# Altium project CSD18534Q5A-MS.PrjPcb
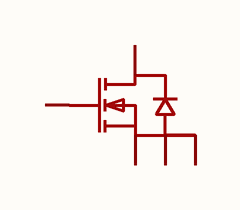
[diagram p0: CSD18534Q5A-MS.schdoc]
1 sheet, 1 parts. Net scope: global (net labels, ports and power ports of the same name join across sheets).

## Sheet CSD18534Q5A-MS.schdoc
size 127 x 101 mm

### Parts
Q?  csd18534q5a-ms  [TDSON-8_L5.9-W5.2-P1.27-BL-1]  (value not drawn)

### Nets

Not connected (* = marked no-connect by the designer): Q? 1(S) 2(S) 3(S) 4(G) 5(D)

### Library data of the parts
Q? = csd18534q5a-ms: 数量:1个N沟道;漏源电压(Vdss):60V;连续漏极电流(Id):65A;导通电阻(RDS(on)):8mΩ@10V;耗散功率(Pd):89W;阈值电压(Vgs(th)):1.6V;; Manufacturer: MSKSEMI(美森科); AddInBom: yes; ModelId: 6d3ef2b64d5a4f2dbd2ee02e0c7053d2; ModelTransform: 205.511,242.1255,0,0,0,0,0,42.913,0; Number: 1个N沟道; Drain to Source Voltage: 60V; Current - Continuous Drain(Id): 65A; Pd - Power Dissipation: 89W; Gate Threshold Voltage (Vgs(th)): 1.6V; Gate Charge(Qg): 19nC; Input Capacitance(Ciss): 930pF; Reverse Transfer Capacitance (Crss@Vds): 20pF; Type: N沟道; Output Capacitance(Coss): 370pF; Vgs: ±20V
